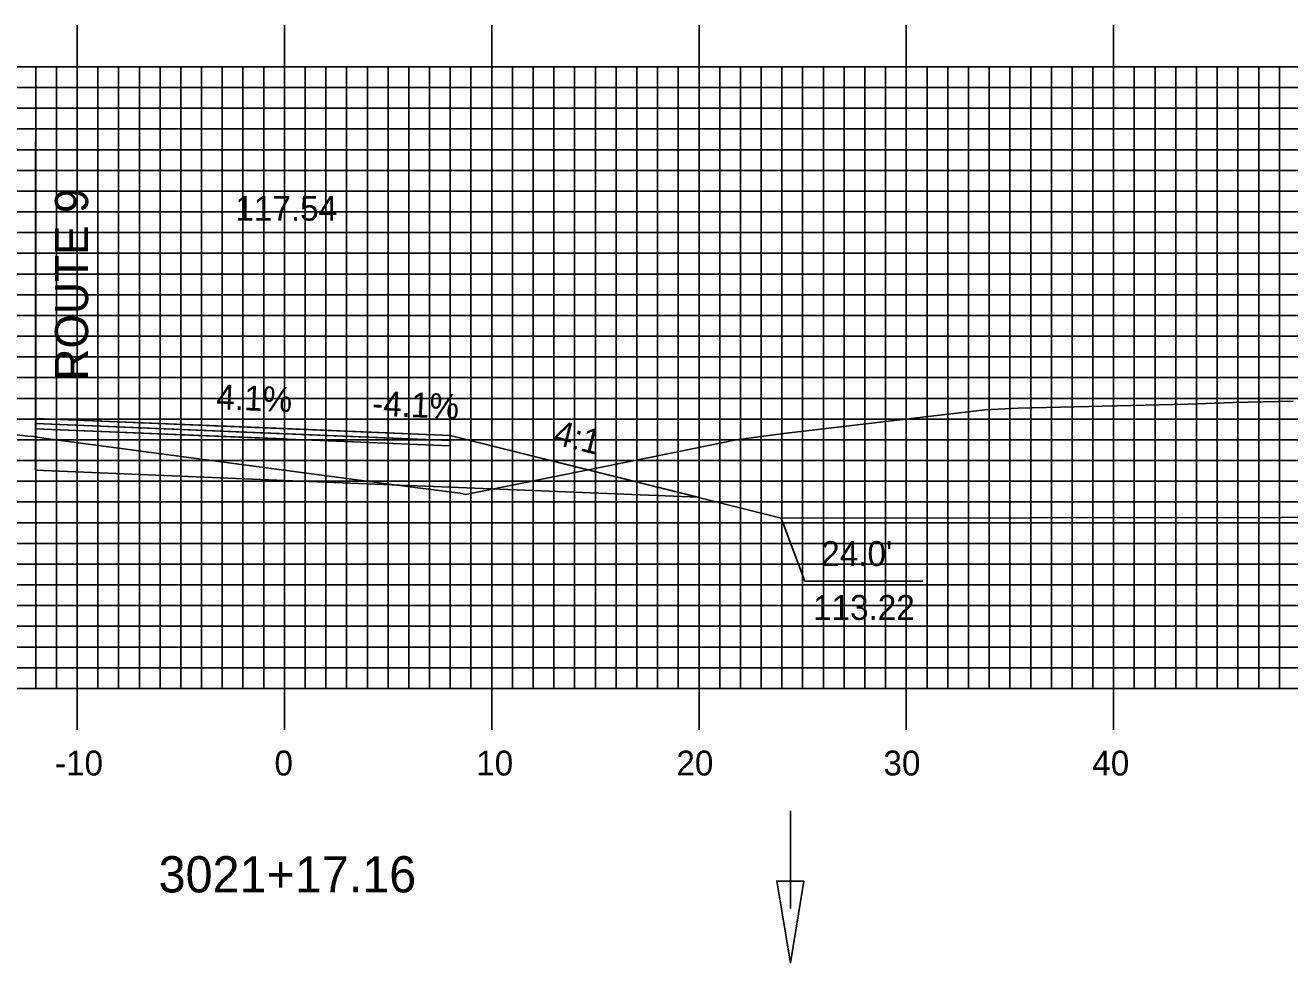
# Model space of a CAD drawing. Extents: x 1686373 to 1686716, y 461260 to 461480.
# Drawn here: x 1686526.3 to 1686587.3, y 461309.8 to 461355.1 of the extents above; entities that cross this region are included whole.
import ezdxf

# ---------------------------------------------------------------- set-up
doc = ezdxf.new("R2010")
doc.units = 0
for name, color, linetype in [('ANNOTATION', 7, 'Continuous'), ('D_Drainage_Ditch_Line', 7, 'Continuous'), ('D_Roadway_Centerline_Text', 7, 'Continuous'), ('D_Roadway_Edge_Shoulder', 7, 'Continuous'), ('D_Roadway_Edge_TW', 7, 'Continuous'), ('D_Roadway_Pavement', 7, 'Continuous'), ('D_Roadway_SlopeLines', 7, 'Continuous'), ('D_Roadway_SubGrade', 7, 'Continuous'), ('H_V ANNOTATION', 7, 'Continuous'), ('MAJOR', 7, 'Continuous'), ('MINOR', 7, 'Continuous'), ('S_Roadway_Centerline', 7, 'Continuous')]:
    doc.layers.add(name, color=color, linetype=linetype)

msp = doc.modelspace()

# ---------------------------------------------------------------- linework, layer by layer
at = {"layer": 'ANNOTATION'}
msp.add_lwpolyline([(1686569.569, 461328.255), (1686563.877, 461328.255), (1686562.725, 461331.296)], dxfattribs=at)
at = {"layer": 'D_Drainage_Ditch_Line'}
msp.add_line((1686563.175, 461312.461), (1686563.175, 461317.16), dxfattribs=at)
msp.add_lwpolyline([(1686563.832, 461313.774), (1686562.519, 461313.774), (1686563.175, 461309.837)], close=True, dxfattribs=at)
at = {"layer": 'D_Roadway_Edge_Shoulder'}
for points in [[(1686526.765, 461336.107), (1686546.765, 461335.287), (1686546.765, 461335.037), (1686526.765, 461335.857)], [(1686526.765, 461335.857), (1686546.765, 461335.037), (1686546.765, 461334.787), (1686526.765, 461335.607)], [(1686538.766, 461335.615), (1686546.765, 461335.287), (1686546.765, 461335.037), (1686538.766, 461335.365)], [(1686538.766, 461335.615), (1686546.765, 461335.287), (1686546.765, 461335.037), (1686538.766, 461335.365)], [(1686538.766, 461335.615), (1686546.765, 461335.287), (1686546.765, 461335.037), (1686538.766, 461335.365)]]:
    msp.add_lwpolyline(points, close=True, dxfattribs=at)
at = {"layer": 'D_Roadway_Edge_TW'}
for points in [[(1686526.765, 461336.107), (1686526.767, 461336.107), (1686526.767, 461335.857), (1686526.765, 461335.857)], [(1686526.765, 461336.107), (1686538.766, 461335.615), (1686538.766, 461335.365), (1686526.765, 461335.857)], [(1686526.765, 461336.107), (1686538.766, 461335.615), (1686538.766, 461335.365), (1686526.765, 461335.857)], [(1686526.765, 461336.107), (1686526.767, 461336.107), (1686526.767, 461335.857), (1686526.765, 461335.857)], [(1686526.767, 461336.107), (1686538.766, 461335.615), (1686538.766, 461335.365), (1686526.767, 461335.857)], [(1686526.767, 461336.107), (1686538.766, 461335.615), (1686538.766, 461335.365), (1686526.767, 461335.857)], [(1686526.767, 461336.107), (1686538.766, 461335.615), (1686538.766, 461335.365), (1686526.767, 461335.857)]]:
    msp.add_lwpolyline(points, close=True, dxfattribs=at)
for points in [[(1686526.767, 461336.107), (1686526.767, 461335.857)], [(1686538.766, 461335.365), (1686538.766, 461335.615)]]:
    msp.add_lwpolyline(points, dxfattribs=at)
at = {"layer": 'D_Roadway_Pavement'}
for points in [[(1686526.765, 461335.857), (1686526.767, 461335.857), (1686526.767, 461335.607), (1686526.765, 461335.607)], [(1686526.765, 461335.857), (1686526.767, 461335.857), (1686526.767, 461335.607), (1686526.765, 461335.607)], [(1686526.765, 461335.857), (1686538.766, 461335.365), (1686538.766, 461335.115), (1686526.765, 461335.607)], [(1686526.765, 461335.857), (1686538.766, 461335.365), (1686538.766, 461335.115), (1686526.765, 461335.607)], [(1686526.767, 461335.857), (1686538.766, 461335.365), (1686538.766, 461335.115), (1686526.767, 461335.607)], [(1686526.767, 461335.857), (1686538.766, 461335.365), (1686538.766, 461335.115), (1686526.767, 461335.607)], [(1686526.767, 461335.857), (1686538.766, 461335.365), (1686538.766, 461335.115), (1686526.767, 461335.607)], [(1686526.767, 461335.857), (1686538.766, 461335.365), (1686538.766, 461335.115), (1686526.767, 461335.607)], [(1686526.767, 461335.857), (1686538.766, 461335.365), (1686538.766, 461335.115), (1686526.767, 461335.607)]]:
    msp.add_lwpolyline(points, close=True, dxfattribs=at)
for points in [[(1686526.765, 461335.857), (1686526.765, 461335.607)], [(1686526.767, 461335.857), (1686526.767, 461335.607)], [(1686538.766, 461335.365), (1686538.766, 461335.115)], [(1686538.766, 461335.365), (1686538.766, 461335.115)], [(1686538.766, 461335.365), (1686538.766, 461335.115)], [(1686538.766, 461335.365), (1686538.766, 461335.115)], [(1686538.766, 461335.365), (1686538.766, 461335.115)], [(1686538.766, 461335.365), (1686538.766, 461335.115)], [(1686538.766, 461335.115), (1686538.766, 461335.365)], [(1686538.766, 461335.365), (1686538.766, 461335.115)]]:
    msp.add_lwpolyline(points, dxfattribs=at)
at = {"layer": 'D_Roadway_SlopeLines'}
for points in [[(1686546.765, 461335.287), (1686562.725, 461331.296)], [(1686546.765, 461335.287), (1686562.725, 461331.296)], [(1686546.765, 461335.287), (1686562.725, 461331.296)], [(1686546.765, 461335.287), (1686562.725, 461331.296)], [(1686562.725, 461331.296), (1686647.215, 461331.409)], [(1686562.725, 461331.296), (1686647.215, 461331.409)], [(1686562.725, 461331.296), (1686647.215, 461331.409)], [(1686562.725, 461331.296), (1686647.215, 461331.409)]]:
    msp.add_lwpolyline(points, dxfattribs=at)
at = {"layer": 'D_Roadway_SubGrade'}
msp.add_line((1686526.767, 461349.486), (1686526.767, 461333.607), dxfattribs=at)
for points in [[(1686526.765, 461335.607), (1686538.766, 461335.115), (1686538.766, 461333.115), (1686526.767, 461333.607)], [(1686526.765, 461335.607), (1686538.766, 461335.115), (1686538.766, 461333.115), (1686526.767, 461333.607)], [(1686526.765, 461335.607), (1686526.767, 461335.607), (1686526.767, 461333.607), (1686526.765, 461333.607)], [(1686526.765, 461335.607), (1686526.767, 461335.607), (1686526.767, 461333.607), (1686526.765, 461333.607)], [(1686526.765, 461335.607), (1686526.767, 461335.607), (1686526.767, 461333.607), (1686526.765, 461333.607)], [(1686526.767, 461335.607), (1686538.766, 461335.115), (1686538.766, 461333.115), (1686526.767, 461333.607)], [(1686526.767, 461335.607), (1686538.766, 461335.115), (1686538.766, 461333.115), (1686526.767, 461333.607)], [(1686526.767, 461335.607), (1686538.766, 461335.115), (1686538.766, 461333.115), (1686526.767, 461333.607)], [(1686538.766, 461333.115), (1686558.724, 461332.296), (1686546.765, 461335.287), (1686546.765, 461335.037), (1686538.766, 461335.365), (1686538.766, 461335.115)], [(1686538.766, 461335.115), (1686538.766, 461335.365), (1686546.765, 461335.037), (1686546.765, 461335.287), (1686558.724, 461332.296), (1686538.766, 461333.115)], [(1686538.766, 461335.115), (1686538.766, 461335.365), (1686546.765, 461335.037), (1686546.765, 461335.287), (1686558.724, 461332.296), (1686538.766, 461333.115)], [(1686538.766, 461333.115), (1686558.724, 461332.296), (1686546.765, 461335.287), (1686546.765, 461335.037), (1686538.766, 461335.365), (1686538.766, 461335.115)]]:
    msp.add_lwpolyline(points, close=True, dxfattribs=at)
msp.add_lwpolyline([(1686526.767, 461335.607), (1686526.767, 461333.607)], dxfattribs=at)
msp.add_lwpolyline([(1686526.767, 461335.607), (1686526.767, 461333.607)], dxfattribs=at)
at = {"layer": 'MAJOR'}
for p, q in [((1686528.769, 461355.076), (1686528.769, 461353.072)), ((1686538.769, 461355.076), (1686538.769, 461353.072)), ((1686548.769, 461355.076), (1686548.769, 461353.072)), ((1686558.769, 461355.076), (1686558.769, 461353.072)), ((1686568.769, 461355.076), (1686568.769, 461353.072)), ((1686578.769, 461355.076), (1686578.769, 461353.072)), ((1686398.769, 461353.072), (1686678.769, 461353.072)), ((1686398.769, 461353.072), (1686678.769, 461353.072)), ((1686528.769, 461323.072), (1686528.769, 461353.072)), ((1686538.769, 461323.072), (1686538.769, 461353.072)), ((1686548.769, 461323.072), (1686548.769, 461353.072)), ((1686558.769, 461323.072), (1686558.769, 461353.072)), ((1686568.769, 461323.072), (1686568.769, 461353.072)), ((1686578.769, 461323.072), (1686578.769, 461353.072)), ((1686398.769, 461348.072), (1686678.769, 461348.072)), ((1686398.769, 461343.072), (1686678.769, 461343.072)), ((1686398.769, 461338.072), (1686678.769, 461338.072)), ((1686398.769, 461333.072), (1686678.769, 461333.072)), ((1686398.769, 461328.072), (1686678.769, 461328.072)), ((1686398.769, 461323.072), (1686678.769, 461323.072)), ((1686398.769, 461323.072), (1686678.769, 461323.072)), ((1686528.769, 461321.068), (1686528.769, 461323.072)), ((1686538.769, 461321.068), (1686538.769, 461323.072)), ((1686548.769, 461321.068), (1686548.769, 461323.072)), ((1686558.769, 461321.068), (1686558.769, 461323.072)), ((1686568.769, 461321.068), (1686568.769, 461323.072)), ((1686578.769, 461321.068), (1686578.769, 461323.072))]:
    msp.add_line(p, q, dxfattribs=at)
at = {"layer": 'MINOR'}
for p, q in [((1686526.769, 461323.072), (1686526.769, 461353.072)), ((1686527.769, 461323.072), (1686527.769, 461353.072)), ((1686529.769, 461323.072), (1686529.769, 461353.072)), ((1686530.769, 461323.072), (1686530.769, 461353.072)), ((1686531.769, 461323.072), (1686531.769, 461353.072)), ((1686532.769, 461323.072), (1686532.769, 461353.072)), ((1686533.769, 461323.072), (1686533.769, 461353.072)), ((1686534.769, 461323.072), (1686534.769, 461353.072)), ((1686535.769, 461323.072), (1686535.769, 461353.072)), ((1686536.769, 461323.072), (1686536.769, 461353.072)), ((1686537.769, 461323.072), (1686537.769, 461353.072)), ((1686539.769, 461323.072), (1686539.769, 461353.072)), ((1686540.769, 461323.072), (1686540.769, 461353.072)), ((1686541.769, 461323.072), (1686541.769, 461353.072)), ((1686542.769, 461323.072), (1686542.769, 461353.072)), ((1686543.769, 461323.072), (1686543.769, 461353.072)), ((1686544.769, 461323.072), (1686544.769, 461353.072)), ((1686545.769, 461323.072), (1686545.769, 461353.072)), ((1686546.769, 461323.072), (1686546.769, 461353.072)), ((1686547.769, 461323.072), (1686547.769, 461353.072)), ((1686549.769, 461323.072), (1686549.769, 461353.072)), ((1686550.769, 461323.072), (1686550.769, 461353.072)), ((1686551.769, 461323.072), (1686551.769, 461353.072)), ((1686552.769, 461323.072), (1686552.769, 461353.072)), ((1686553.769, 461323.072), (1686553.769, 461353.072)), ((1686554.769, 461323.072), (1686554.769, 461353.072)), ((1686555.769, 461323.072), (1686555.769, 461353.072)), ((1686556.769, 461323.072), (1686556.769, 461353.072)), ((1686557.769, 461323.072), (1686557.769, 461353.072)), ((1686559.769, 461323.072), (1686559.769, 461353.072)), ((1686560.769, 461323.072), (1686560.769, 461353.072)), ((1686561.769, 461323.072), (1686561.769, 461353.072)), ((1686562.769, 461323.072), (1686562.769, 461353.072)), ((1686563.769, 461323.072), (1686563.769, 461353.072)), ((1686564.769, 461323.072), (1686564.769, 461353.072)), ((1686565.769, 461323.072), (1686565.769, 461353.072)), ((1686566.769, 461323.072), (1686566.769, 461353.072)), ((1686567.769, 461323.072), (1686567.769, 461353.072)), ((1686569.769, 461323.072), (1686569.769, 461353.072)), ((1686570.769, 461323.072), (1686570.769, 461353.072)), ((1686571.769, 461323.072), (1686571.769, 461353.072)), ((1686572.769, 461323.072), (1686572.769, 461353.072)), ((1686573.769, 461323.072), (1686573.769, 461353.072)), ((1686574.769, 461323.072), (1686574.769, 461353.072)), ((1686575.769, 461323.072), (1686575.769, 461353.072)), ((1686576.769, 461323.072), (1686576.769, 461353.072)), ((1686577.769, 461323.072), (1686577.769, 461353.072)), ((1686579.769, 461323.072), (1686579.769, 461353.072)), ((1686580.769, 461323.072), (1686580.769, 461353.072)), ((1686581.769, 461323.072), (1686581.769, 461353.072)), ((1686582.769, 461323.072), (1686582.769, 461353.072)), ((1686583.769, 461323.072), (1686583.769, 461353.072)), ((1686584.769, 461323.072), (1686584.769, 461353.072)), ((1686585.769, 461323.072), (1686585.769, 461353.072)), ((1686586.769, 461323.072), (1686586.769, 461353.072)), ((1686398.769, 461352.072), (1686678.769, 461352.072)), ((1686398.769, 461351.072), (1686678.769, 461351.072)), ((1686398.769, 461350.072), (1686678.769, 461350.072)), ((1686398.769, 461349.072), (1686678.769, 461349.072)), ((1686398.769, 461347.072), (1686678.769, 461347.072)), ((1686398.769, 461346.072), (1686678.769, 461346.072)), ((1686398.769, 461345.072), (1686678.769, 461345.072)), ((1686398.769, 461344.072), (1686678.769, 461344.072)), ((1686398.769, 461342.072), (1686678.769, 461342.072)), ((1686398.769, 461341.072), (1686678.769, 461341.072)), ((1686398.769, 461340.072), (1686678.769, 461340.072)), ((1686398.769, 461339.072), (1686678.769, 461339.072)), ((1686398.769, 461337.072), (1686678.769, 461337.072)), ((1686398.769, 461336.072), (1686678.769, 461336.072)), ((1686398.769, 461335.072), (1686678.769, 461335.072)), ((1686398.769, 461334.072), (1686678.769, 461334.072)), ((1686398.769, 461332.072), (1686678.769, 461332.072)), ((1686398.769, 461331.072), (1686678.769, 461331.072)), ((1686398.769, 461330.072), (1686678.769, 461330.072)), ((1686398.769, 461329.072), (1686678.769, 461329.072)), ((1686398.769, 461327.072), (1686678.769, 461327.072)), ((1686398.769, 461326.072), (1686678.769, 461326.072)), ((1686398.769, 461325.072), (1686678.769, 461325.072)), ((1686398.769, 461324.072), (1686678.769, 461324.072))]:
    msp.add_line(p, q, dxfattribs=at)
at = {"layer": 'S_Roadway_Centerline'}
msp.add_lwpolyline([(1686525.617, 461335.351), (1686526.396, 461335.255), (1686526.67, 461335.225), (1686527.256, 461335.131), (1686544.185, 461332.888), (1686547.246, 461332.49), (1686547.515, 461332.425), (1686557.734, 461334.487), (1686560.566, 461335.064), (1686562.489, 461335.326), (1686562.868, 461335.38), (1686572.554, 461336.522), (1686574.166, 461336.598), (1686582.337, 461336.786), (1686584.545, 461336.87), (1686587.425, 461336.941)], dxfattribs=at)

# ---------------------------------------------------------------- texts
at = {"layer": 'ANNOTATION'}
for s, height, rotation, p in [('ROUTE 9', 1.6, 90, (1686529.298, 461337.93)), ('4.1%', 1.2, 357.65178, (1686535.467, 461336.552)), ('-4.1%', 1.2, 357.65304, (1686542.981, 461336.244)), ('4:1', 1.2, 345.96004, (1686551.688, 461334.878))]:
    msp.add_text(s, height=height, rotation=rotation, dxfattribs=at).set_placement(p)
for s, p in [("24.0' ", (1686564.666, 461328.981)), ('113.22', (1686564.27, 461326.381))]:
    msp.add_text(s, height=1.2, dxfattribs=at).set_placement(p)
at = {"layer": 'D_Roadway_Centerline_Text'}
msp.add_text('117.54', height=1.2, dxfattribs=at).set_placement((1686536.404, 461345.645))
at = {"layer": 'H_V ANNOTATION'}
for s, height, p in [('-10', 1.2, (1686527.698, 461318.872)), ('0', 1.2, (1686538.287, 461318.872)), ('10', 1.2, (1686548.019, 461318.872)), ('20', 1.2, (1686557.677, 461318.872)), ('30', 1.2, (1686567.666, 461318.872)), ('40', 1.2, (1686577.741, 461318.872)), ('3021+17.16', 1.75, (1686532.698, 461313.228))]:
    msp.add_text(s, height=height, dxfattribs=at).set_placement(p)

doc.saveas('drawing.dxf')
